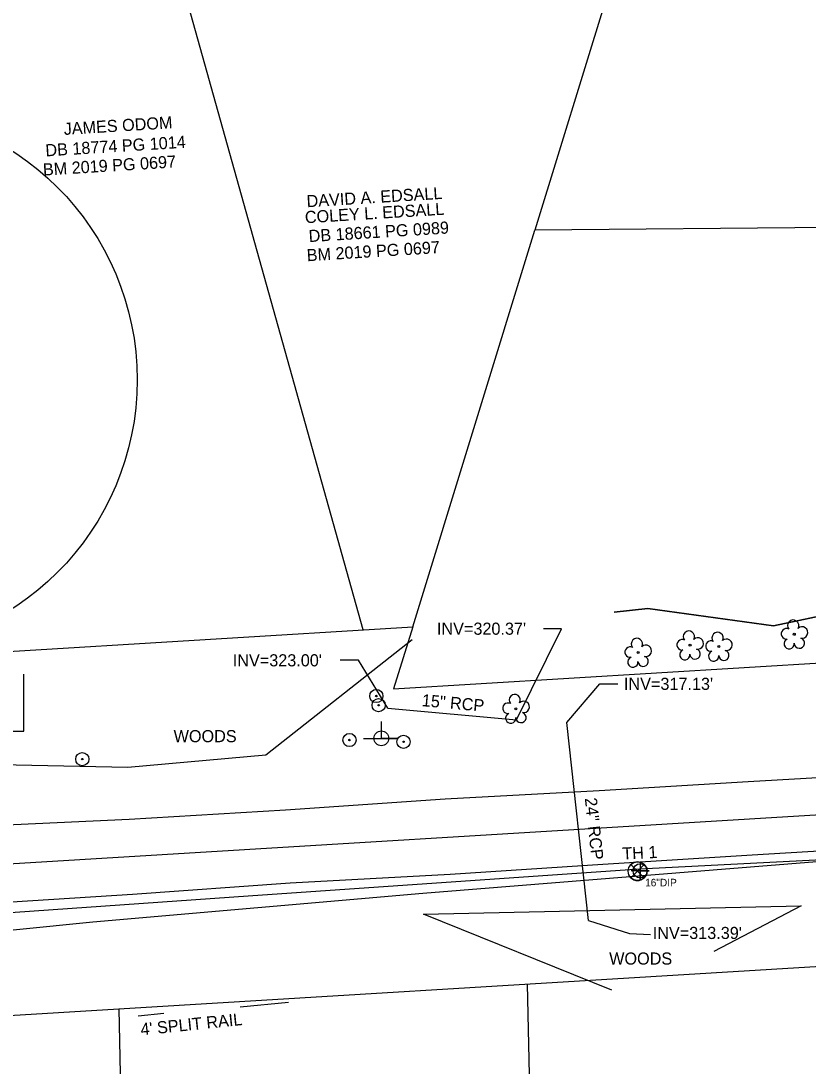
# Model space of a CAD drawing. Extents: x 2110969 to 2113691, y 670003 to 672285.
# Drawn here: x 2111607.7 to 2111867.6, y 670375.7 to 670720.8 of the extents above; entities that cross this region are included whole.
import ezdxf

# ---------------------------------------------------------------- set-up
doc = ezdxf.new("R2010")
doc.units = 0
for name, color, linetype in [('Exist DTM Regular Point CELL', 7, 'Continuous'), ('Exist Horizontal Alignment', 7, 'Continuous'), ('Exist Other Culture Anchor (Guy Wire) CELL', 7, 'Continuous'), ('Exist Other Culture Fence Line', 7, 'Continuous'), ('Exist Other Culture Fence Line Text', 7, 'Continuous'), ('Exist Property Deed Book Text', 7, 'Continuous'), ('Exist Property Line', 7, 'Continuous'), ('Exist Property Owner Text', 7, 'Continuous'), ('Exist Right of Way Line', 7, 'Continuous'), ('Exist Roads EOP', 7, 'Continuous'), ('Exist Structure Minor Pipes RCP 15 Inch', 7, 'Continuous'), ('Exist Structure Minor Pipes RCP 15 Inch Invert', 7, 'Continuous'), ('Exist Structure Minor Pipes RCP 15 Inch Leader', 7, 'Continuous'), ('Exist Structure Minor Pipes RCP 15 Inch Text', 7, 'Continuous'), ('Exist Structure Minor Pipes RCP 24 Inch', 7, 'Continuous'), ('Exist Structure Minor Pipes RCP 24 Inch Invert', 7, 'Continuous'), ('Exist Structure Minor Pipes RCP 24 Inch Leader', 7, 'Continuous'), ('Exist Structure Minor Pipes RCP 24 Inch Text', 7, 'Continuous'), ('Exist Utilities Power Joint Use Telephone CELL', 7, 'Continuous'), ('Exist Utilities Telephone UG FO SUE LOS B', 7, 'Continuous'), ('Exist Utilities Water Test Hole SUE LOS A CELL', 7, 'Continuous'), ('Exist Utilities Water Test Hole SUE LOS A Cogo Comment', 7, 'Continuous'), ('Exist Utilities Water Test Hole SUE LOS A Text', 7, 'Continuous'), ('Exist Utilities Water UG Line SUE LOS C', 7, 'Continuous'), ('Exist Vegetation Hedge Row', 7, 'Continuous'), ('Exist Vegetation Tree CELL', 7, 'Continuous'), ('Exist Vegetation Woods Line', 7, 'Continuous'), ('Exist Vegetation Woods Line Text', 7, 'Continuous')]:
    doc.layers.add(name, color=color, linetype=linetype)

msp = doc.modelspace()

# ---------------------------------------------------------------- linework, layer by layer
at = {"layer": 'Exist DTM Regular Point CELL'}
msp.add_lwpolyline([(2111812.18, 670443.22), (2111812.18, 670437.22), (2111812.18, 670440.22), (2111815.18, 670440.22), (2111809.18, 670440.22)], dxfattribs=at)
msp.add_circle((2111812.18, 670440.22), 2.34, dxfattribs=at)
at = {"layer": 'Exist Horizontal Alignment'}
msp.add_line((2111597.13, 670442.15), (2113362.13, 670549.12), dxfattribs=at)
at = {"layer": 'Exist Other Culture Anchor (Guy Wire) CELL'}
for centre, radius in [((2111725.08, 670497.93), 2.18), ((2111725.08, 670497.93), 0.24), ((2111725.84, 670494.9), 2.18), ((2111725.84, 670494.9), 0.24), ((2111716.21, 670483.39), 2.18), ((2111716.21, 670483.39), 0.24), ((2111734.06, 670482.81), 2.18), ((2111734.06, 670482.81), 0.24), ((2111628.01, 670477.1), 2.18), ((2111628.01, 670477.1), 0.24)]:
    msp.add_circle(centre, radius, dxfattribs=at)
at = {"layer": 'Exist Other Culture Fence Line'}
for p, q in [((2111696.13, 670396.78), (2111680.13, 670395.17)), ((2111654.91, 670393.09), (2111646.46, 670392.22))]:
    msp.add_line(p, q, dxfattribs=at)
at = {"layer": 'Exist Property Line'}
for p, q in [((2111840.14, 670855.73), (2111777.37, 670651.74)), ((2111720.69, 670519.77), (2111633.08, 670833.33)), ((2111956.32, 670653.26), (2111777.37, 670651.74)), ((2111737.08, 670520.76), (2111777.37, 670651.74)), ((2111780.63, 670136.93), (2111775.04, 670402.84)), ((2111645.66, 670134.1), (2111640.18, 670394.67))]:
    msp.add_line(p, q, dxfattribs=at)
msp.add_circle((2111556.12, 670602.32), 90, dxfattribs=at)
at = {"layer": 'Exist Right of Way Line'}
for p, q in [((2111510.41, 670507.03), (2111737.08, 670520.76)), ((2111737.08, 670520.76), (2111730.8, 670500.35)), ((2111730.8, 670500.35), (2111949.35, 670513.59)), ((2111600.16, 670392.24), (2112086.29, 670421.71))]:
    msp.add_line(p, q, dxfattribs=at)
at = {"layer": 'Exist Roads EOP'}
for points in [[(2111588.73, 670454.74), (2111643.53, 670457.25), (2111695.12, 670460.35), (2111747.76, 670463.95), (2111798.61, 670466.79), (2111847.8, 670469.72), (2111895.71, 670472.43), (2111931.59, 670475.09), (2111949.32, 670483.37), (2111960.18, 670508.31), (2111965.31, 670535.61), (2111966.42, 670566.2)], [(2111113.04, 670379.86), (2111152.42, 670385.43), (2111198.84, 670391.51), (2111251.82, 670398.21), (2111301.73, 670404.04), (2111354.14, 670410.05), (2111403.51, 670414.77), (2111454.4, 670419.12), (2111510.63, 670423.98), (2111568.62, 670427.85), (2111590.78, 670429.08), (2111644.59, 670432.49), (2111696.66, 670436.2), (2111749.46, 670439.16), (2111799.83, 670442.46), (2111849.2, 670445.5), (2111896.91, 670448.39), (2111943.04, 670451.41), (2111983.3, 670453.57), (2112026.46, 670456.2), (2112076.66, 670459.13), (2112122.85, 670461.54), (2112125.88, 670459.79)]]:
    msp.add_lwpolyline(points, dxfattribs=at)
at = {"layer": 'Exist Structure Minor Pipes RCP 15 Inch'}
msp.add_line((2111728.86, 670493.88), (2111771.38, 670490.04), dxfattribs=at)
at = {"layer": 'Exist Structure Minor Pipes RCP 15 Inch Leader'}
for points in [[(2111771.38, 670490.04), (2111786.22, 670520.16), (2111780.22, 670520.16)], [(2111728.86, 670493.88), (2111719.14, 670509.72), (2111713.14, 670509.72)]]:
    msp.add_lwpolyline(points, dxfattribs=at)
at = {"layer": 'Exist Structure Minor Pipes RCP 24 Inch'}
msp.add_line((2111795.1, 670423.85), (2111787.93, 670489.17), dxfattribs=at)
at = {"layer": 'Exist Structure Minor Pipes RCP 24 Inch Leader'}
for points in [[(2111787.93, 670489.17), (2111798.83, 670501.96), (2111804.83, 670501.96)], [(2111795.1, 670423.85), (2111808.7, 670419.55), (2111815.6, 670419.22)]]:
    msp.add_lwpolyline(points, dxfattribs=at)
at = {"layer": 'Exist Utilities Power Joint Use Telephone CELL'}
msp.add_line((2111726.75, 670483.94), (2111726.75, 670483.94), dxfattribs=at)
msp.add_lwpolyline([(2111720.81, 670483.94), (2111732.15, 670483.9), (2111726.75, 670483.92), (2111726.75, 670489.56)], dxfattribs=at)
msp.add_circle((2111726.75, 670483.95), 2.45, dxfattribs=at)
at = {"layer": 'Exist Utilities Telephone UG FO SUE LOS B'}
msp.add_lwpolyline([(2111579.85, 670418.18), (2111631.45, 670423.41), (2111740.38, 670432.81), (2111885.62, 670444.53), (2111926.38, 670441.18), (2111977.11, 670441.9), (2112063.2, 670445.72), (2112109.68, 670453.08), (2112138.77, 670453.18), (2112237, 670457.87), (2112306.5, 670460.33), (2112380.27, 670463.6), (2112482.83, 670468.65), (2112529.94, 670475.11), (2112581.42, 670479.39), (2112613.55, 670486.14), (2112667.68, 670491.25), (2112816.71, 670501.11)], dxfattribs=at)
msp.add_lwpolyline([(2111579.85, 670418.18), (2111631.45, 670423.41), (2111740.38, 670432.81), (2111885.62, 670444.53), (2111926.38, 670441.18), (2111977.11, 670441.9), (2112063.2, 670445.72), (2112109.68, 670453.08), (2112138.77, 670453.18), (2112237, 670457.87), (2112306.5, 670460.33), (2112380.27, 670463.6), (2112482.83, 670468.65), (2112529.94, 670475.11), (2112581.42, 670479.39), (2112613.55, 670486.14), (2112667.68, 670491.25), (2112816.71, 670501.11)], dxfattribs=at)
at = {"layer": 'Exist Utilities Water Test Hole SUE LOS A CELL'}
for points in [[(2111813.47, 670442.26), (2111809.13, 670437.92), (2111811.3, 670440.09), (2111809.13, 670442.26), (2111813.47, 670437.92)], [(2111809.13, 670442.26), (2111811.3, 670440.09), (2111813.47, 670442.26)], [(2111813.47, 670437.92), (2111811.3, 670440.09), (2111809.13, 670437.92)]]:
    msp.add_lwpolyline(points, dxfattribs=at)
msp.add_circle((2111811.3, 670440.09), 3.07, dxfattribs=at)
for start, end in [(45, 135), (225, 315)]:
    msp.add_arc((2111811.3, 670440.09), 3.07, start, end, dxfattribs=at)
at = {"layer": 'Exist Utilities Water UG Line SUE LOS C'}
msp.add_lwpolyline([(2111426.66, 670411.76), (2111552.37, 670422.8), (2111682.74, 670431.91), (2111812.01, 670440.88), (2111917.46, 670446.23), (2112062.93, 670452.85)], dxfattribs=at)
msp.add_lwpolyline([(2111426.66, 670411.76), (2111552.37, 670422.8), (2111682.74, 670431.91), (2111812.01, 670440.88), (2111917.46, 670446.23), (2112062.93, 670452.85)], dxfattribs=at)
at = {"layer": 'Exist Vegetation Hedge Row'}
for points in [[(2111878.14, 670525.76), (2111856.24, 670521.06), (2111814.71, 670526.8), (2111803.55, 670525.57)], [(2111803.55, 670525.57), (2111814.71, 670526.8), (2111856.24, 670521.06), (2111878.14, 670525.76)]]:
    msp.add_lwpolyline(points, dxfattribs=at)
at = {"layer": 'Exist Vegetation Tree CELL'}
for p, q in [((2111863.07, 670518.3), (2111863.07, 670518.3)), ((2111828.64, 670514.68), (2111828.64, 670514.68)), ((2111811.48, 670512.28), (2111811.48, 670512.28)), ((2111838.13, 670514.26), (2111838.13, 670514.26)), ((2111771.16, 670493.73), (2111771.16, 670493.73))]:
    msp.add_line(p, q, dxfattribs=at)
for centre in [(2111863.07, 670518.3), (2111828.64, 670514.68), (2111838.13, 670514.26), (2111811.48, 670512.28), (2111771.16, 670493.73)]:
    msp.add_circle(centre, 0.326, dxfattribs=at)
for centre, radius, start, end in [((2111862.69, 670521.18), 1.86, 330.1651, 219.7134), ((2111828.26, 670517.55), 1.86, 330.1651, 219.7134), ((2111837.75, 670517.13), 1.86, 330.1651, 219.7134), ((2111860.47, 670518.46), 1.73, 62.6636, 279.3457), ((2111865.62, 670518.89), 1.9, 257.1011, 134.1999), ((2111811.1, 670515.15), 1.86, 330.1651, 219.7134), ((2111814.03, 670512.86), 1.9, 257.1011, 134.1999), ((2111826.04, 670514.83), 1.73, 62.6636, 279.3457), ((2111831.19, 670515.27), 1.9, 257.1011, 134.1999), ((2111835.53, 670514.41), 1.73, 62.6636, 279.3457), ((2111840.68, 670514.85), 1.9, 257.1011, 134.1999), ((2111861.37, 670515.18), 1.69, 111.5671, 6.231), ((2111864.75, 670515.4), 1.7, 181.2822, 74.56), ((2111808.88, 670512.43), 1.73, 62.6636, 279.3457), ((2111826.94, 670511.56), 1.69, 111.5671, 6.231), ((2111830.31, 670511.78), 1.7, 181.2822, 74.56), ((2111836.43, 670511.14), 1.69, 111.5671, 6.231), ((2111839.81, 670511.36), 1.7, 181.2822, 74.56), ((2111809.78, 670509.16), 1.69, 111.5671, 6.231), ((2111813.16, 670509.38), 1.7, 181.2822, 74.56), ((2111770.78, 670496.6), 1.86, 330.1651, 219.7134), ((2111768.55, 670493.88), 1.73, 62.6636, 279.3457), ((2111773.71, 670494.32), 1.9, 257.1011, 134.1999), ((2111769.46, 670490.61), 1.69, 111.5671, 6.231), ((2111772.83, 670490.83), 1.7, 181.2822, 74.56)]:
    msp.add_arc(centre, radius, start, end, dxfattribs=at)
at = {"layer": 'Exist Vegetation Woods Line'}
for p, q in [((2111740.65, 670425.86), (2111865.29, 670428.67)), ((2111865.29, 670428.67), (2111836.49, 670413.58)), ((2111802.79, 670400.8), (2111740.64, 670425.86))]:
    msp.add_line(p, q, dxfattribs=at)
msp.add_lwpolyline([(2111736.87, 670516.43), (2111688.58, 670478.4), (2111643.02, 670474.38), (2111574.41, 670475.81), (2111540.78, 670482.38), (2111527.85, 670493.41), (2111564.64, 670486.33), (2111608.73, 670486.38), (2111608.69, 670505.14)], dxfattribs=at)

# ---------------------------------------------------------------- texts
at = {"layer": 'Exist Other Culture Fence Line Text'}
msp.add_text("4' SPLIT RAIL", height=4, rotation=5.8638, dxfattribs=at).set_placement((2111647.43, 670385.87))
at = {"layer": 'Exist Property Deed Book Text'}
for s, p in [('DB 18774 PG 1014', (2111615.95, 670676.07)), ('BM 2019 PG 0697', (2111615.13, 670669.72)), ('DB 18661 PG 0989', (2111702.86, 670647.78)), ('BM 2019 PG 0697', (2111702.23, 670641.45))]:
    msp.add_text(s, height=4, rotation=3.5509, dxfattribs=at).set_placement(p)
at = {"layer": 'Exist Property Owner Text'}
for s, p in [('JAMES ODOM', (2111621.98, 670683.15)), ('DAVID A. EDSALL', (2111702.17, 670659.28)), ('COLEY L. EDSALL', (2111701.62, 670653.98))]:
    msp.add_text(s, height=4, rotation=3.5509, dxfattribs=at).set_placement(p)
at = {"layer": 'Exist Structure Minor Pipes RCP 15 Inch Invert'}
for s, p in [("INV=320.37'", (2111745.09, 670518.16)), ("INV=323.00'", (2111677.69, 670507.72))]:
    msp.add_text(s, height=4, dxfattribs=at).set_placement(p)
at = {"layer": 'Exist Structure Minor Pipes RCP 15 Inch Text'}
msp.add_text('15" RCP', height=4, rotation=354.8398, dxfattribs=at).set_placement((2111739.97, 670494.6))
at = {"layer": 'Exist Structure Minor Pipes RCP 24 Inch Invert'}
for s, p in [("INV=317.13'", (2111806.83, 670499.96)), ("INV=313.39'", (2111816.34, 670417.71))]:
    msp.add_text(s, height=4, dxfattribs=at).set_placement(p)
at = {"layer": 'Exist Structure Minor Pipes RCP 24 Inch Text'}
msp.add_text('24" RCP', height=4, rotation=276.2609, dxfattribs=at).set_placement((2111793.89, 670464.16))
at = {"layer": 'Exist Utilities Water Test Hole SUE LOS A Cogo Comment'}
msp.add_text('16"DIP', height=2.5, dxfattribs=at).set_placement((2111813.8, 670435.09))
at = {"layer": 'Exist Utilities Water Test Hole SUE LOS A Text'}
msp.add_text('TH 1', height=4, rotation=2.7668, dxfattribs=at).set_placement((2111806.38, 670443.91))
at = {"layer": 'Exist Vegetation Woods Line Text'}
for p in [(2111658.16, 670482.68), (2111801.95, 670409.26)]:
    msp.add_text('WOODS', height=4, dxfattribs=at).set_placement(p)

doc.saveas('drawing.dxf')
